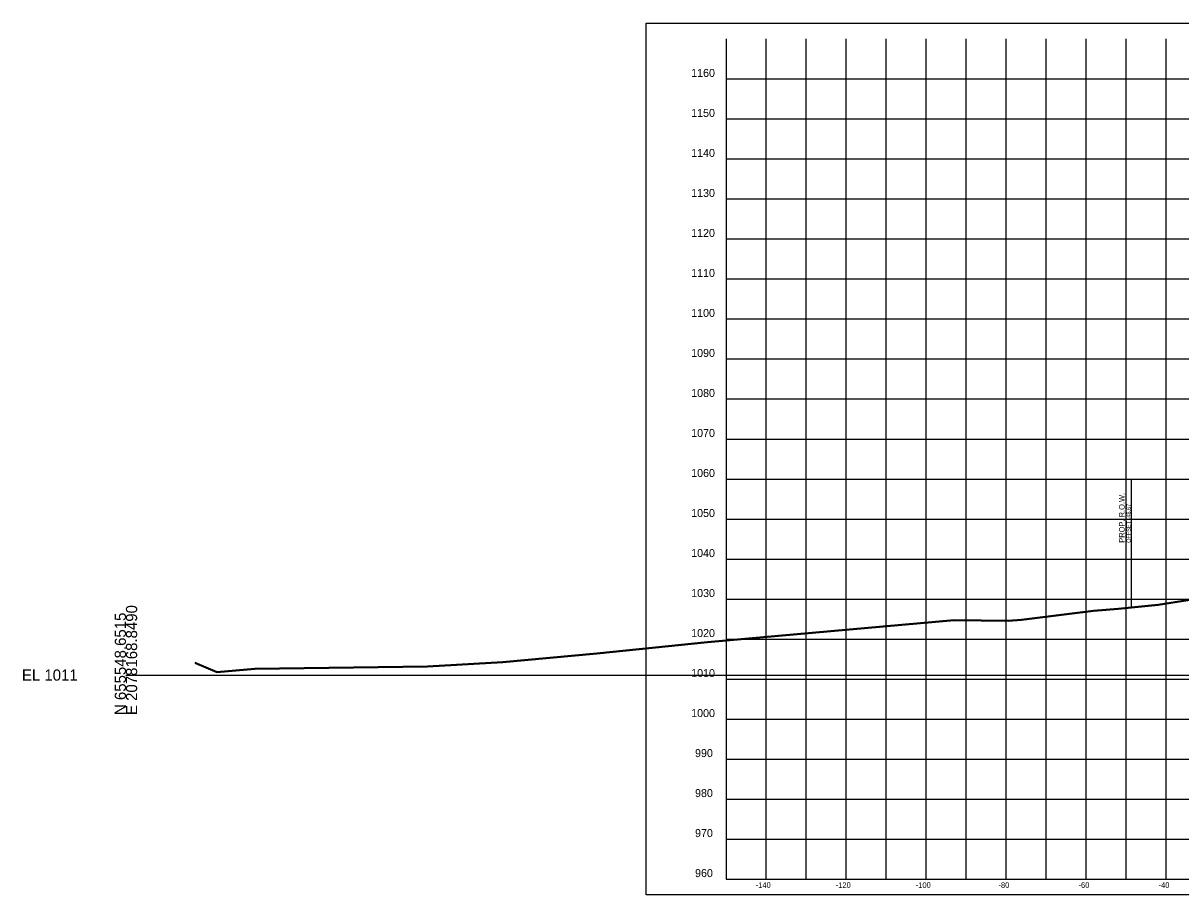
# Model space of a CAD drawing. Extents: x 5868 to 6683, y 2883 to 19120.
# Drawn here: x 5868.1 to 6157.4, y 5890.1 to 6108 of the extents above; entities that cross this region are included whole.
import ezdxf

# ---------------------------------------------------------------- set-up
doc = ezdxf.new("R2010")
doc.units = 0
for name, color, linetype in [('DESIGN - ROW - Right-of-Way and Easement Labels', 7, 'Continuous'), ('DESIGN - ROW - Right-of-Way Linework', 7, 'Continuous'), ('DESIGN - SHEET - Corner Text', 7, 'Continuous'), ('DESIGN - SHEET - Light Grid', 7, 'Continuous'), ('DESIGN - SHEET - Linework', 7, 'Continuous'), ('DESIGN - SHEET - Plot Shape', 7, 'Continuous'), ('SURVEY - GROUND - Bottom of Topsoil Layer', 7, 'Continuous'), ('SURVEY - GROUND - Top of Ground', 7, 'Continuous')]:
    doc.layers.add(name, color=color, linetype=linetype)

msp = doc.modelspace()

# ---------------------------------------------------------------- linework, layer by layer
at = {"layer": 'DESIGN - ROW - Right-of-Way Linework'}
msp.add_line((6145.11, 5962.13), (6145.11, 5994.13), dxfattribs=at)
at = {"layer": 'DESIGN - SHEET - Light Grid'}
msp.add_line((5893.78, 5945.07), (6193.78, 5945.07), dxfattribs=at)
at = {"layer": 'DESIGN - SHEET - Linework'}
for p, q in [((6053.78, 5894.07), (6053.78, 6104.07)), ((6063.78, 5894.07), (6063.78, 6104.07)), ((6073.78, 5894.07), (6073.78, 6104.07)), ((6083.78, 5894.07), (6083.78, 6104.07)), ((6093.78, 5894.07), (6093.78, 6104.07)), ((6103.78, 5894.07), (6103.78, 6104.07)), ((6113.78, 5894.07), (6113.78, 6104.07)), ((6123.78, 5894.07), (6123.78, 6104.07)), ((6133.78, 5894.07), (6133.78, 6104.07)), ((6143.78, 5894.07), (6143.78, 6104.07)), ((6153.78, 5894.07), (6153.78, 6104.07)), ((6043.78, 6094.07), (6343.78, 6094.07)), ((6043.78, 6084.07), (6343.78, 6084.07)), ((6043.78, 6074.07), (6343.78, 6074.07)), ((6043.78, 6064.07), (6343.78, 6064.07)), ((6043.78, 6054.07), (6343.78, 6054.07)), ((6043.78, 6044.07), (6343.78, 6044.07)), ((6043.78, 6034.07), (6343.78, 6034.07)), ((6043.78, 6024.07), (6343.78, 6024.07)), ((6043.78, 6014.07), (6343.78, 6014.07)), ((6043.78, 6004.07), (6343.78, 6004.07)), ((6043.78, 5994.07), (6343.78, 5994.07)), ((6043.78, 5984.07), (6343.78, 5984.07)), ((6043.78, 5974.07), (6343.78, 5974.07)), ((6043.78, 5964.07), (6343.78, 5964.07)), ((6043.78, 5954.07), (6343.78, 5954.07)), ((6043.78, 5944.07), (6343.78, 5944.07)), ((6043.78, 5934.07), (6343.78, 5934.07)), ((6043.78, 5924.07), (6343.78, 5924.07)), ((6043.78, 5914.07), (6343.78, 5914.07)), ((6043.78, 5904.07), (6343.78, 5904.07))]:
    msp.add_line(p, q, dxfattribs=at)
msp.add_lwpolyline([(6043.78, 6104.07), (6043.78, 5894.07), (6343.78, 5894.07), (6343.78, 6104.07)], dxfattribs=at)
at = {"layer": 'DESIGN - SHEET - Plot Shape'}
msp.add_lwpolyline([(6023.78, 6108.01), (6363.78, 6108.01), (6363.78, 5890.13), (6023.78, 5890.13)], close=True, dxfattribs=at)
at = {"layer": 'SURVEY - GROUND - Bottom of Topsoil Layer'}
for p, q in [((6151.71, 5962.55), (6174.6, 5966.16)), ((6117.58, 5958.75), (6135.54, 5961.01)), ((6135.54, 5961.01), (6141.73, 5961.53)), ((6141.73, 5961.53), (6151.71, 5962.55)), ((6039.14, 5953.22), (6100.77, 5958.73)), ((6100.77, 5958.73), (6114.24, 5958.54)), ((6114.24, 5958.54), (6117.58, 5958.75)), ((6011.46, 5950.4), (6039.14, 5953.22)), ((5987.96, 5948.2), (6011.46, 5950.4)), ((5910.96, 5948.03), (5916.53, 5945.67)), ((5916.53, 5945.67), (5925.99, 5946.52)), ((5925.99, 5946.52), (5969.15, 5947.11)), ((5969.15, 5947.11), (5987.96, 5948.2))]:
    msp.add_line(p, q, dxfattribs=at)
at = {"layer": 'SURVEY - GROUND - Top of Ground'}
msp.add_lwpolyline([(5910.96, 5948.28), (5916.53, 5945.92), (5925.99, 5946.77), (5969.15, 5947.36), (5987.96, 5948.45), (6011.46, 5950.65), (6039.14, 5953.47), (6100.77, 5958.98), (6114.24, 5958.79), (6117.58, 5959), (6135.54, 5961.26), (6141.73, 5961.78), (6151.71, 5962.8), (6174.6, 5966.41)], dxfattribs=at)

# ---------------------------------------------------------------- texts
at = {"layer": 'DESIGN - ROW - Right-of-Way and Easement Labels'}
for s, height, p in [('PROP. R.O.W.', 1.4, (6143.36, 5978.13)), ('OFFSET -48.67', 1, (6144.86, 5978.13))]:
    msp.add_text(s, height=height, rotation=90, dxfattribs=at).set_placement(p)
at = {"layer": 'DESIGN - SHEET - Corner Text'}
for s, height, p in [('1160', 2, (6035.03, 6094.57)), ('1150', 2, (6035.03, 6084.57)), ('1140', 2, (6035.03, 6074.57)), ('1130', 2, (6035.03, 6064.57)), ('1120', 2, (6035.03, 6054.57)), ('1110', 2, (6035.03, 6044.57)), ('1100', 2, (6035.03, 6034.57)), ('1090', 2, (6035.03, 6024.57)), ('1080', 2, (6035.03, 6014.57)), ('1070', 2, (6035.03, 6004.57)), ('1060', 2, (6035.03, 5994.57)), ('1050', 2, (6035.03, 5984.57)), ('1040', 2, (6035.03, 5974.57)), ('1030', 2, (6035.03, 5964.57)), ('1020', 2, (6035.03, 5954.57)), ('1010', 2, (6035.03, 5944.57)), ('1000', 2, (6035.03, 5934.57)), ('990', 2, (6036, 5924.57)), ('980', 2, (6036, 5914.57)), ('970', 2, (6036, 5904.57)), ('960', 2, (6036, 5894.57)), ('-140', 1.4, (6051.16, 5891.87)), ('-120', 1.4, (6071.16, 5891.87)), ('-100', 1.4, (6091.16, 5891.87)), ('-80', 1.4, (6111.84, 5891.87)), ('-60', 1.4, (6131.84, 5891.87)), ('-40', 1.4, (6151.84, 5891.87))]:
    msp.add_text(s, height=height, dxfattribs=at).set_placement(p)
at = {"layer": 'DESIGN - SHEET - Light Grid'}
for s, p in [('N 655548.6515', (5893.78, 5935.07)), ('E 2078168.8490', (5896.58, 5935.07))]:
    msp.add_text(s, height=2.8, rotation=90, dxfattribs=at).set_placement(p)
msp.add_text('EL 1011', height=2.8, dxfattribs=at).set_placement((5867.78, 5943.67))

doc.saveas('drawing.dxf')
